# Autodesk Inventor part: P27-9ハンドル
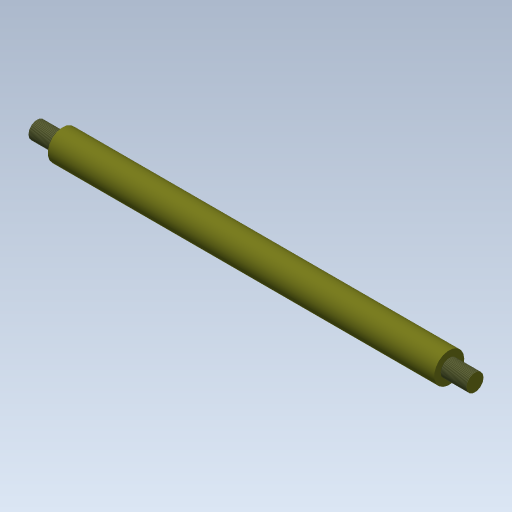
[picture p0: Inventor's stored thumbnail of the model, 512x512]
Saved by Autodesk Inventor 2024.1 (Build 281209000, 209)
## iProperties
Created: 2008-07
Part Number: P27-9ハンドル
Document SubType Name: Modeling
Designer: y-shimohigashi
Density: 1 g/cm^3
Stock Number: P24-9ハンドル
Material: 一般
Appearance: Green Meteorite
Author: y-shimohigashi
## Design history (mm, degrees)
revolve "回転1" stored, may be unused: angle "d4" = 90 deg
feature "ねじ1" dims "d5" = 10, "d6" = 0
feature "ねじ2" dims "d7" = 10, "d8" = 0
node "ソリッド1"
node "ソリッド ボディ"
node "サーフェス ボディ"
sketch "スケッチ1"
  geometry: L1 (-102, 0)-(102, 0); L2 (-102, 0)-(-102, 4); L3 (-102, 4)-(-90, 4); L4 (-90, 4)-(-90, 7); L5 (-90, 7)-(90, 7); L6 (90, 7)-(90, 4); L7 (90, 4)-(102, 4); L8 (102, 4)-(102, 0); 2 further points
  constraints: 16 end point, 4 parallel, 3 collinear, 2 perpendicular, 1 coincident, 1 horizontal, 1 midpoint
  dimensions: "d0" = 7 distance between parallel lines of L1 L5; "d1" = 4 distance of L7.end L1.end; "d2" = 180 distance of L4.end L5.end; "d3" = 12 distance of L6.end L7.end
